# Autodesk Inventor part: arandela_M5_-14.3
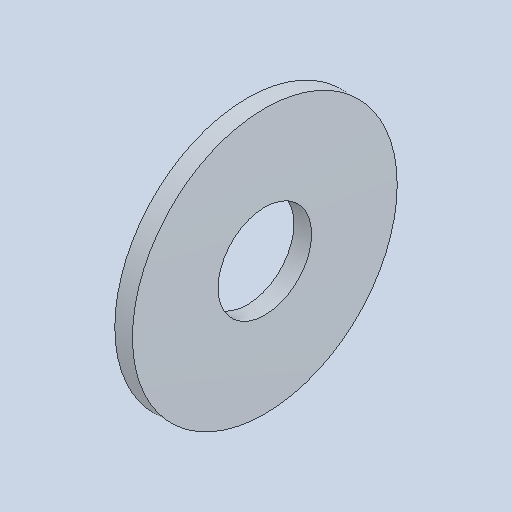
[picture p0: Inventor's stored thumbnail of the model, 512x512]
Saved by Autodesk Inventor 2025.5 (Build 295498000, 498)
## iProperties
Created: 2026-10
Part Number: arandela_M5_-14.3
Material: Genérico
Document SubType Name: Modeling
Designer: Luis M
Density: 1 g/cm^3
Appearance: Valor por defecto
Author: Luis M
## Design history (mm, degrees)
feature "Base1"
node "Sólido1"
